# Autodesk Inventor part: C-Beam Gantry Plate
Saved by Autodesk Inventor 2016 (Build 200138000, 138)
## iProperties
Created: 2015-11
Part Number: C-Beam Gantry Plate
Material: Generic
Document SubType Name: Modeling
Designer: John
Density: 1 g/cm^3
Appearance: Default
Author: John
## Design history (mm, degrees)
feature "SOLID1"
body "Solid1"
